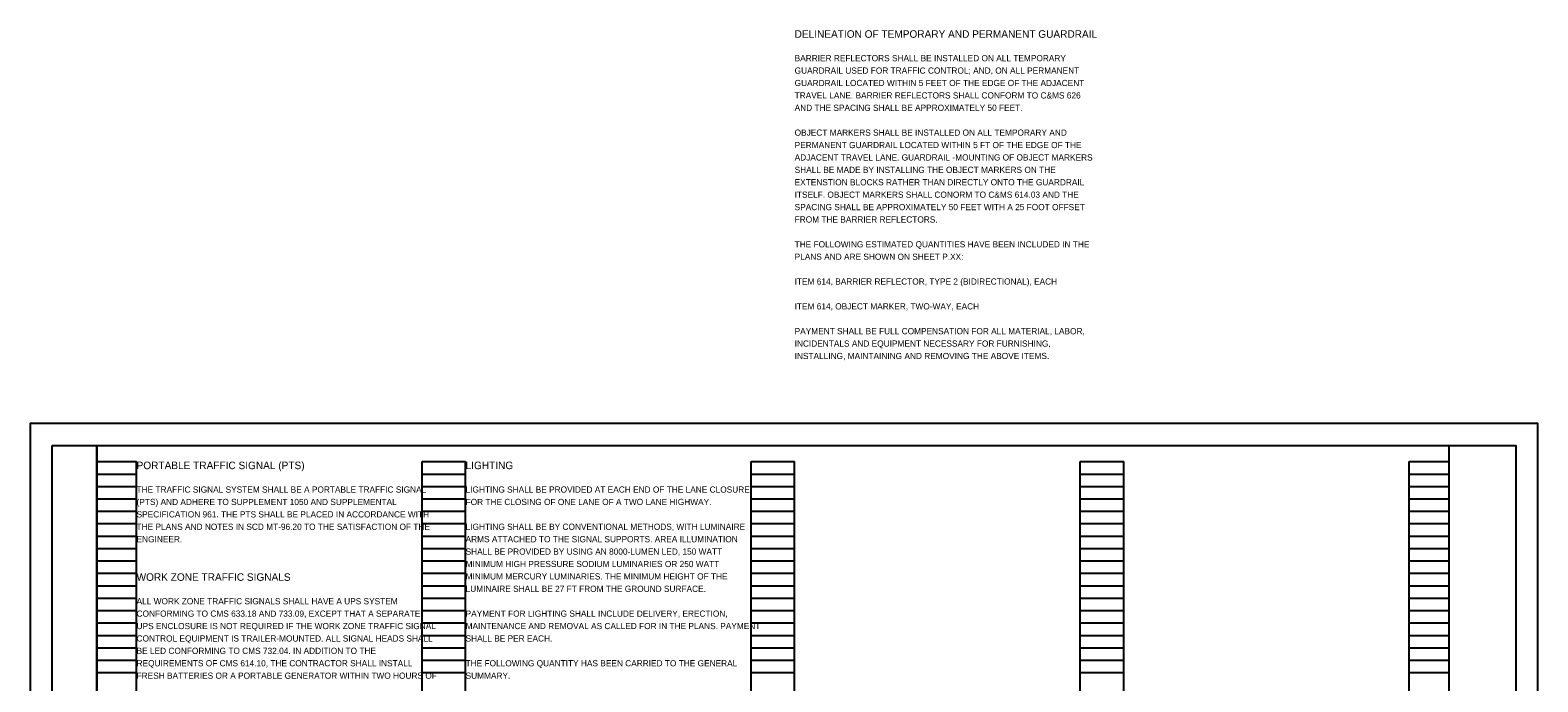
# Model space of a CAD drawing. Extents: x 0 to 34, y -4.2 to 30.9.
# Drawn here: x 0 to 34, y 16.17 to 30.88 of the extents above; entities that cross this region are included whole.
import ezdxf

# ---------------------------------------------------------------- set-up
doc = ezdxf.new("R2010")
doc.units = 0
for name, color, linetype in [('Default', 7, 'Continuous'), ('SH_Border', 7, 'Continuous'), ('SH_Cut_Line', 7, 'Continuous'), ('SH_Data', 7, 'Continuous'), ('SH_Text', 7, 'Continuous')]:
    doc.layers.add(name, color=color, linetype=linetype)

msp = doc.modelspace()

# ---------------------------------------------------------------- linework, layer by layer
at = {"layer": 'SH_Border'}
msp.add_line((32, 0.5), (32, 21.5), dxfattribs=at)
for points in [[(0.5, 21.5), (1.5, 21.5), (1.5, 0.5), (0.5, 0.5)], [(1.5, 21.5), (33.5, 21.5), (33.5, 0.5), (1.5, 0.5)]]:
    msp.add_lwpolyline(points, close=True, dxfattribs=at)
at = {"layer": 'SH_Cut_Line'}
msp.add_lwpolyline([(0, 0), (34, 0), (34, 22), (0, 22)], close=True, dxfattribs=at)
at = {"layer": 'SH_Data'}
for p, q in [((1.5, 0.98), (1.5, 21.14)), ((1.5, 21.14), (2.4, 21.14)), ((2.4, 0.98), (2.4, 21.14)), ((8.84, 0.98), (8.84, 21.14)), ((8.84, 21.14), (9.82, 21.14)), ((9.82, 0.98), (9.82, 21.14)), ((16.26, 0.98), (16.26, 21.14)), ((16.26, 21.14), (17.24, 21.14)), ((17.24, 0.98), (17.24, 21.14)), ((23.68, 0.98), (23.68, 21.14)), ((23.68, 21.14), (24.66, 21.14)), ((24.66, 0.98), (24.66, 21.14)), ((31.1, 0.98), (31.1, 21.14)), ((31.1, 21.14), (32, 21.14)), ((32, 0.98), (32, 21.14)), ((1.5, 20.86), (2.4, 20.86)), ((8.84, 20.86), (9.82, 20.86)), ((16.26, 20.86), (17.24, 20.86)), ((23.68, 20.86), (24.66, 20.86)), ((31.1, 20.86), (32, 20.86)), ((1.5, 20.58), (2.4, 20.58)), ((8.84, 20.58), (9.82, 20.58)), ((16.26, 20.58), (17.24, 20.58)), ((23.68, 20.58), (24.66, 20.58)), ((31.1, 20.58), (32, 20.58)), ((1.5, 20.3), (2.4, 20.3)), ((8.84, 20.3), (9.82, 20.3)), ((16.26, 20.3), (17.24, 20.3)), ((23.68, 20.3), (24.66, 20.3)), ((31.1, 20.3), (32, 20.3)), ((1.5, 20.02), (2.4, 20.02)), ((1.5, 19.74), (2.4, 19.74)), ((8.84, 20.02), (9.82, 20.02)), ((8.84, 19.74), (9.82, 19.74)), ((16.26, 20.02), (17.24, 20.02)), ((16.26, 19.74), (17.24, 19.74)), ((23.68, 20.02), (24.66, 20.02)), ((23.68, 19.74), (24.66, 19.74)), ((31.1, 20.02), (32, 20.02)), ((31.1, 19.74), (32, 19.74)), ((1.5, 19.46), (2.4, 19.46)), ((8.84, 19.46), (9.82, 19.46)), ((16.26, 19.46), (17.24, 19.46)), ((23.68, 19.46), (24.66, 19.46)), ((31.1, 19.46), (32, 19.46)), ((1.5, 19.18), (2.4, 19.18)), ((8.84, 19.18), (9.82, 19.18)), ((16.26, 19.18), (17.24, 19.18)), ((23.68, 19.18), (24.66, 19.18)), ((31.1, 19.18), (32, 19.18)), ((1.5, 18.9), (2.4, 18.9)), ((8.84, 18.9), (9.82, 18.9)), ((16.26, 18.9), (17.24, 18.9)), ((23.68, 18.9), (24.66, 18.9)), ((31.1, 18.9), (32, 18.9)), ((1.5, 18.62), (2.4, 18.62)), ((8.84, 18.62), (9.82, 18.62)), ((16.26, 18.62), (17.24, 18.62)), ((23.68, 18.62), (24.66, 18.62)), ((31.1, 18.62), (32, 18.62)), ((1.5, 18.34), (2.4, 18.34)), ((1.5, 18.06), (2.4, 18.06)), ((8.84, 18.34), (9.82, 18.34)), ((8.84, 18.06), (9.82, 18.06)), ((16.26, 18.34), (17.24, 18.34)), ((16.26, 18.06), (17.24, 18.06)), ((23.68, 18.34), (24.66, 18.34)), ((23.68, 18.06), (24.66, 18.06)), ((31.1, 18.34), (32, 18.34)), ((31.1, 18.06), (32, 18.06)), ((1.5, 17.78), (2.4, 17.78)), ((8.84, 17.78), (9.82, 17.78)), ((16.26, 17.78), (17.24, 17.78)), ((23.68, 17.78), (24.66, 17.78)), ((31.1, 17.78), (32, 17.78)), ((1.5, 17.5), (2.4, 17.5)), ((8.84, 17.5), (9.82, 17.5)), ((16.26, 17.5), (17.24, 17.5)), ((23.68, 17.5), (24.66, 17.5)), ((31.1, 17.5), (32, 17.5)), ((1.5, 17.22), (2.4, 17.22)), ((8.84, 17.22), (9.82, 17.22)), ((16.26, 17.22), (17.24, 17.22)), ((23.68, 17.22), (24.66, 17.22)), ((31.1, 17.22), (32, 17.22)), ((1.5, 16.94), (2.4, 16.94)), ((8.84, 16.94), (9.82, 16.94)), ((16.26, 16.94), (17.24, 16.94)), ((23.68, 16.94), (24.66, 16.94)), ((31.1, 16.94), (32, 16.94)), ((1.5, 16.66), (2.4, 16.66)), ((1.5, 16.38), (2.4, 16.38)), ((8.84, 16.66), (9.82, 16.66)), ((8.84, 16.38), (9.82, 16.38)), ((16.26, 16.66), (17.24, 16.66)), ((16.26, 16.38), (17.24, 16.38)), ((23.68, 16.66), (24.66, 16.66)), ((23.68, 16.38), (24.66, 16.38)), ((31.1, 16.66), (32, 16.66)), ((31.1, 16.38), (32, 16.38))]:
    msp.add_line(p, q, dxfattribs=at)

# ---------------------------------------------------------------- texts
at = {"layer": 'Default'}
for s, p in [('BARRIER REFLECTORS SHALL BE INSTALLED ON ALL TEMPORARY ', (17.24, 30.174)), ('GUARDRAIL USED FOR TRAFFIC CONTROL; AND, ON ALL PERMANENT ', (17.24, 29.894)), ('GUARDRAIL LOCATED WITHIN 5 FEET OF THE EDGE OF THE ADJACENT ', (17.24, 29.614)), ('TRAVEL LANE. BARRIER REFLECTORS SHALL CONFORM TO C&MS 626 ', (17.24, 29.334)), ('AND THE SPACING SHALL BE APPROXIMATELY 50 FEET.', (17.24, 29.054)), ('OBJECT MARKERS SHALL BE INSTALLED ON ALL TEMPORARY AND ', (17.24, 28.494)), ('PERMANENT GUARDRAIL LOCATED WITHIN 5 FT OF THE EDGE OF THE ', (17.24, 28.214)), ('ADJACENT TRAVEL LANE. GUARDRAIL -MOUNTING OF OBJECT MARKERS ', (17.24, 27.934)), ('SHALL BE MADE BY INSTALLING THE OBJECT MARKERS ON THE ', (17.24, 27.654)), ('EXTENSTION BLOCKS RATHER THAN DIRECTLY ONTO THE GUARDRAIL ', (17.24, 27.374)), ('ITSELF. OBJECT MARKERS SHALL CONORM TO C&MS 614.03 AND THE ', (17.24, 27.094)), ('SPACING SHALL BE APPROXIMATELY 50 FEET WITH A 25 FOOT OFFSET ', (17.24, 26.814)), ('FROM THE BARRIER REFLECTORS.', (17.24, 26.534)), ('THE FOLLOWING ESTIMATED QUANTITIES HAVE BEEN INCLUDED IN THE ', (17.24, 25.974)), ('PLANS AND ARE SHOWN ON SHEET P.XX:', (17.24, 25.694)), ('ITEM 614, BARRIER REFLECTOR, TYPE 2 (BIDIRECTIONAL), EACH', (17.24, 25.134)), ('ITEM 614, OBJECT MARKER, TWO-WAY, EACH', (17.24, 24.574)), ('PAYMENT SHALL BE FULL COMPENSATION FOR ALL MATERIAL, LABOR, ', (17.24, 24.014)), ('INCIDENTALS AND EQUIPMENT NECESSARY FOR FURNISHING, ', (17.24, 23.734)), ('INSTALLING, MAINTAINING AND REMOVING THE ABOVE ITEMS.', (17.24, 23.454)), ('LIGHTING SHALL BE PROVIDED AT EACH END OF THE LANE CLOSURE ', (9.82, 20.44)), ('FOR THE CLOSING OF ONE LANE OF A TWO LANE HIGHWAY.', (9.82, 20.16)), ('LIGHTING SHALL BE BY CONVENTIONAL METHODS, WITH LUMINAIRE ', (9.82, 19.6)), ('ARMS ATTACHED TO THE SIGNAL SUPPORTS. AREA ILLUMINATION ', (9.82, 19.32)), ('SHALL BE PROVIDED BY USING AN 8000-LUMEN LED, 150 WATT ', (9.82, 19.04)), ('MINIMUM HIGH PRESSURE SODIUM LUMINARIES OR 250 WATT ', (9.82, 18.76)), ('MINIMUM MERCURY LUMINARIES. THE MINIMUM HEIGHT OF THE ', (9.82, 18.48)), ('LUMINAIRE SHALL BE 27 FT FROM THE GROUND SURFACE.', (9.82, 18.2)), ('PAYMENT FOR LIGHTING SHALL INCLUDE DELIVERY, ERECTION, ', (9.82, 17.64)), ('MAINTENANCE AND REMOVAL AS CALLED FOR IN THE PLANS. PAYMENT ', (9.82, 17.36)), ('SHALL BE PER EACH.', (9.82, 17.08)), ('THE FOLLOWING QUANTITY HAS BEEN CARRIED TO THE GENERAL ', (9.82, 16.52)), ('SUMMARY.', (9.82, 16.24))]:
    msp.add_text(s, height=0.14, dxfattribs=at).set_placement(p)
at = {"layer": 'SH_Text'}
for s, height, p in [('DELINEATION OF TEMPORARY AND PERMANENT GUARDRAIL', 0.17, (17.24, 30.704)), ('PORTABLE TRAFFIC SIGNAL (PTS)', 0.17, (2.4, 20.97)), ('LIGHTING', 0.17, (9.82, 20.97)), ('THE TRAFFIC SIGNAL SYSTEM SHALL BE A PORTABLE TRAFFIC SIGNAL ', 0.14, (2.4, 20.44)), ('(PTS) AND ADHERE TO SUPPLEMENT 1050 AND SUPPLEMENTAL ', 0.14, (2.4, 20.16)), ('THE PLANS AND NOTES IN SCD MT-96.20 TO THE SATISFACTION OF THE ', 0.14, (2.4, 19.6)), ('SPECIFICATION 961. THE PTS SHALL BE PLACED IN ACCORDANCE WITH ', 0.14, (2.4, 19.88)), ('ENGINEER. ', 0.14, (2.4, 19.32)), ('WORK ZONE TRAFFIC SIGNALS', 0.17, (2.4, 18.45)), ('ALL WORK ZONE TRAFFIC SIGNALS SHALL HAVE A UPS SYSTEM ', 0.14, (2.4, 17.92)), ('CONFORMING TO CMS 633.18 AND 733.09, EXCEPT THAT A SEPARATE ', 0.14, (2.4, 17.64)), ('UPS ENCLOSURE IS NOT REQUIRED IF THE WORK ZONE TRAFFIC SIGNAL ', 0.14, (2.4, 17.36)), ('CONTROL EQUIPMENT IS TRAILER-MOUNTED. ALL SIGNAL HEADS SHALL ', 0.14, (2.4, 17.08)), ('BE LED CONFORMING TO CMS 732.04. IN ADDITION TO THE ', 0.14, (2.4, 16.8)), ('REQUIREMENTS OF CMS 614.10, THE CONTRACTOR SHALL INSTALL ', 0.14, (2.4, 16.52)), ('FRESH BATTERIES OR A PORTABLE GENERATOR WITHIN TWO HOURS OF ', 0.14, (2.4, 16.24))]:
    msp.add_text(s, height=height, dxfattribs=at).set_placement(p)

doc.saveas('drawing.dxf')
